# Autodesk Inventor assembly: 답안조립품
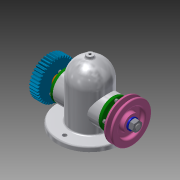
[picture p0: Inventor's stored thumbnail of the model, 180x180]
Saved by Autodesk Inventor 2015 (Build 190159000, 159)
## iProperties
Created: 2019-11
Part Number: 답안조립품
Document SubType Name: Assembly
Designer: now
Author: now
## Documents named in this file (14)
- C:\Users\now\Desktop\491104V1036\답안조립품.iam
- C:\Users\now\Desktop\491104V1036\V-벨트풀리.ipt
- V-벨트풀리.ipt
- C:\Users\now\Desktop\491104V1036\너트 M12x1.25.ipt
- C:\Users\now\Desktop\491104V1036\베어링 6203.ipt
- C:\Users\now\Desktop\491104V1036\본체.ipt
- C:\Users\now\Desktop\491104V1036\볼트 M4.ipt
- C:\Users\now\Desktop\491104V1036\부시.ipt
- C:\Users\now\Desktop\491104V1036\스퍼기어.ipt
- C:\Users\now\Desktop\491104V1036\오일 실 26 38 8.ipt
- C:\Users\now\Desktop\491104V1036\와셔 12x24.ipt
- C:\Users\now\Desktop\491104V1036\축.ipt
- C:\Users\now\Desktop\491104V1036\커버.ipt
- C:\Users\now\Desktop\491104V1036\키 5x5x12.ipt
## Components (1 placed, 1 different names)
1. V-벨트풀리:1 — 각도:4
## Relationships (1: Angle 1)
- 각도:4 [Angle]: V-벨트풀리:1
